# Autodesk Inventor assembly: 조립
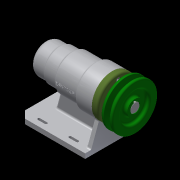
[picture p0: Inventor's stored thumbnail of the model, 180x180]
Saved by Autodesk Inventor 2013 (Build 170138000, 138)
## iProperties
Created: 2017-09
Part Number: 조립
Document SubType Name: Assembly
Designer: Administrator
Author: Administrator
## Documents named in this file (12)
- C:\Users\Administrator\Desktop\470908V1004\조립.iam
- C:\Users\Administrator\Desktop\470908V1004\1. 본체.ipt
- C:\Users\Administrator\Desktop\470908V1004\커버.ipt
- C:\Users\Administrator\Desktop\470908V1004\축.ipt
- C:\Users\Administrator\Desktop\470908V1004\베어링 6004.ipt
- C:\Users\Administrator\Desktop\470908V1004\어댑터슬리브.ipt
- C:\Users\Administrator\Desktop\470908V1004\베어링 51202.ipt
- C:\Users\Administrator\Desktop\470908V1004\키 5 x 5 x 16.ipt
- C:\Users\Administrator\Desktop\470908V1004\V벨트풀리.ipt
- C:\Users\Administrator\Desktop\470908V1004\멈춤나사 M3x8.ipt
- C:\Users\Administrator\Desktop\470908V1004\볼트 M4 x 12.ipt
- C:\Users\Administrator\Desktop\470908V1004\오일 실 20x35x7.ipt
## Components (2 placed, 2 different names)
1. 1. 본체:1 — 각도:2
2. V벨트풀리:1
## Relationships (1: Angle 1)
- 각도:2 [Angle]: 1. 본체:1
